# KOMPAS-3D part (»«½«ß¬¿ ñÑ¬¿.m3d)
File: created 22.07.2016 15:30:02, last saved 22.07.2016 15:35:07.
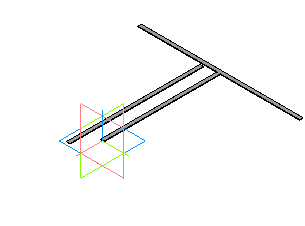
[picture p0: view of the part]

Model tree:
1. Эскиз:1
2. Операция выдавливания:1
     Толщина стенки 1 = 2; Толщина стенки 2 = 2; Расстояние 1 = 0.8
3. Эскиз:2
4. Операция выдавливания:2
     Толщина стенки 1 = 2; Толщина стенки 2 = 2; Расстояние 1 = 0.8
5. Эскиз:3
6. Операция выдавливания:3
     Толщина стенки 1 = 2; Толщина стенки 2 = 2; Расстояние 1 = 0.8
7. Эскиз:4
8. Вырезать элемент выдавливания:1
     Толщина стенки 1 = 2; Толщина стенки 2 = 2; Расстояние 1 = 10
